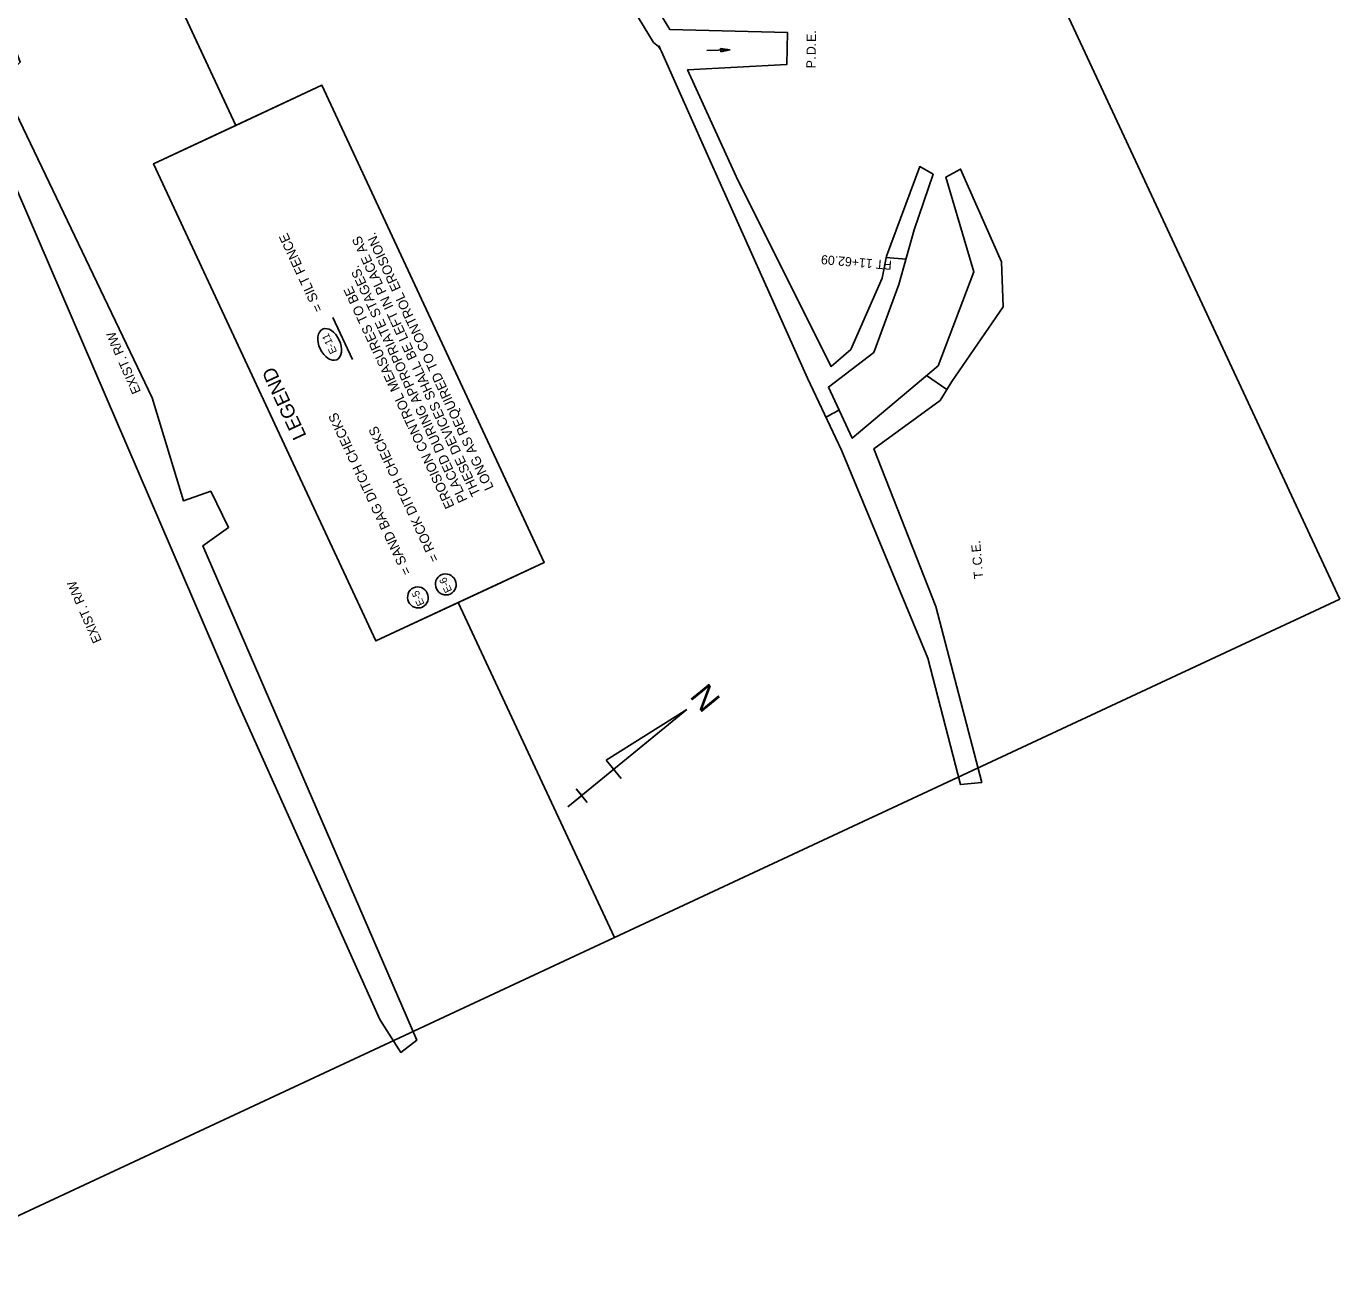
# Model space of a CAD drawing. Extents: x 964229 to 965790, y 1899262 to 1901428.
# Drawn here: x 964934 to 965790, y 1899262 to 1900076 of the extents above; entities that cross this region are included whole.
import ezdxf

# ---------------------------------------------------------------- set-up
doc = ezdxf.new("R2010")
doc.units = 0
for name, color, linetype in [('1', 7, 'Continuous'), ('43', 7, 'Continuous'), ('63', 7, 'Continuous'), ('Level 1', 7, 'Continuous'), ('Level 44', 7, 'Continuous'), ('NO PLOT', 7, 'Continuous'), ('R_Draft', 7, 'Continuous'), ('R_Horz Alg', 7, 'Continuous'), ('R_Horz Alg Annot', 7, 'Continuous')]:
    doc.layers.add(name, color=color, linetype=linetype)

msp = doc.modelspace()

# ---------------------------------------------------------------- linework, layer by layer
at = {"layer": '1'}
for p, q in [((965070.98, 1900011.03), (964950.03, 1900270.4)), ((965126.95, 1900037.14), (965017.24, 1899985.98)), ((965162.05, 1899675.42), (965017.24, 1899985.98)), ((965241.02, 1899712.24), (965162.05, 1899675.42)), ((965317.44, 1899482.49), (965215.79, 1899700.48))]:
    msp.add_line(p, q, dxfattribs=at)
msp.add_lwpolyline([(965241.02, 1899712.24), (965271.77, 1899726.58), (965126.95, 1900037.14)], dxfattribs=at)
at = {"layer": '43'}
for p, q in [((965386.67, 1900058.98), (965386.6, 1900061.13)), ((965386.6, 1900061.13), (965392.71, 1900060.24)), ((965392.71, 1900060.24), (965386.67, 1900058.98))]:
    msp.add_line(p, q, dxfattribs=at)
msp.add_lwpolyline([(965377.53, 1900059.77), (965392.71, 1900060.24)], dxfattribs=at)
at = {"layer": '63'}
for p, q in [((965287.19, 1899567.51), (965364.58, 1899630.84)), ((965364.58, 1899630.84), (965305.05, 1899582.13)), ((965364.58, 1899630.84), (965312.08, 1899597.82)), ((965312.08, 1899597.82), (965321.82, 1899585.92)), ((965287.19, 1899567.51), (965305.05, 1899582.13)), ((965296.12, 1899574.82), (965292.46, 1899579.28)), ((965292.46, 1899579.28), (965299.77, 1899570.35)), ((965287.19, 1899567.51), (965296.12, 1899574.82))]:
    msp.add_line(p, q, dxfattribs=at)
at = {"layer": 'Level 1'}
for centre, major_axis, ratio in [((965132.03, 1899868.45), (-4.63, 9.93), 0.622952), ((965207.6, 1899712.22), (2.91, -6.24), 0.97521), ((965189.47, 1899703.76), (2.91, -6.24), 0.97521)]:
    msp.add_ellipse(centre, major_axis=major_axis, ratio=ratio, dxfattribs=at)
at = {"layer": 'Level 44'}
msp.add_lwpolyline([(965146.86, 1899858.74), (965134.12, 1899886.04)], dxfattribs=at)
at = {"layer": 'NO PLOT'}
for points in [[(965789.77, 1899702.74), (965115.54, 1901148.63), (964643.21, 1900928.38), (964770.42, 1900655.58), (964831.6, 1900684.11), (965011.21, 1900298.93), (964950.03, 1900270.4), (965070.98, 1900011.03), (965126.95, 1900037.14), (965271.77, 1899726.58), (965215.79, 1899700.48), (965317.44, 1899482.49)], [(965789.77, 1899702.74), (965115.54, 1901148.63), (964643.21, 1900928.38), (964770.42, 1900655.58), (964831.6, 1900684.11), (965011.21, 1900298.93), (964950.03, 1900270.4), (965070.98, 1900011.03), (965126.95, 1900037.14), (965271.77, 1899726.58), (965215.79, 1899700.48), (965317.44, 1899482.49)], [(965789.77, 1899702.74), (965115.54, 1901148.63), (964643.21, 1900928.38), (964770.42, 1900655.58), (964831.6, 1900684.11), (965011.21, 1900298.93), (964950.03, 1900270.4), (965070.98, 1900011.03), (965126.95, 1900037.14), (965271.77, 1899726.58), (965215.79, 1899700.48), (965317.44, 1899482.49)], [(964845.11, 1899262.24), (964344.7, 1900335.36), (964389.48, 1900356.24), (964306.73, 1900533.69), (964319.96, 1900539.86), (964228.89, 1900735.17), (964643.21, 1900928.38), (964770.42, 1900655.58), (964700.63, 1900623.04), (964880.25, 1900237.86), (964950.03, 1900270.4), (965070.98, 1900011.03), (965017.24, 1899985.98), (965162.05, 1899675.42), (965215.79, 1899700.48), (965317.44, 1899482.49)], [(964845.11, 1899262.24), (964344.7, 1900335.36), (964389.48, 1900356.24), (964306.73, 1900533.69), (964319.96, 1900539.86), (964228.89, 1900735.17), (964643.21, 1900928.38), (964770.42, 1900655.58), (964700.63, 1900623.04), (964880.25, 1900237.86), (964950.03, 1900270.4), (965070.98, 1900011.03), (965017.24, 1899985.98), (965162.05, 1899675.42), (965215.79, 1899700.48), (965317.44, 1899482.49)], [(964845.11, 1899262.24), (964344.7, 1900335.36), (964389.48, 1900356.24), (964306.73, 1900533.69), (964319.96, 1900539.86), (964228.89, 1900735.17), (964643.21, 1900928.38), (964770.42, 1900655.58), (964700.63, 1900623.04), (964880.25, 1900237.86), (964950.03, 1900270.4), (965070.98, 1900011.03), (965017.24, 1899985.98), (965162.05, 1899675.42), (965215.79, 1899700.48), (965317.44, 1899482.49)], [(965347.31, 1900060.65), (965346.28, 1900062.47), (965346.24, 1900062.45), (965347.28, 1900060.63)]]:
    msp.add_lwpolyline(points, close=True, dxfattribs=at)
for points in [[(964743.2, 1900380.79), (964921.35, 1899985.44), (965071.82, 1899636.13), (965164.72, 1899429.12), (965178.4, 1899407.57), (965188.68, 1899415.47), (965049.43, 1899737.41), (965066.12, 1899749.34), (965054.6, 1899772.93), (965036.81, 1899766.7), (965016.41, 1899833.74), (964918.01, 1900039.22), (964930.54, 1900052.3), (964920.78, 1900078.79), (964905.36, 1900075.22), (964854.38, 1900212.3)], [(965291.71, 1900149.32), (965342.96, 1900065.1), (965346.17, 1900062.34), (965346.6, 1900062.65), (965346.62, 1900062.57), (965347.35, 1900060.46), (965347.33, 1900060.4), (965347.59, 1900060.06), (965348.08, 1900059.15), (965377.94, 1899992.37), (965443.26, 1899846.6), (965465.34, 1899799.73), (965521.63, 1899664.21), (965542.72, 1899581.94), (965556.69, 1899583.34), (965526.85, 1899697.97), (965486.39, 1899800.6), (965529.54, 1899831.99), (965537.16, 1899844.35), (965570.5, 1899893), (965569.59, 1899922.15), (965542.83, 1899982.57), (965533.26, 1899977.4), (965551.42, 1899915.79), (965528.16, 1899854.59), (965472.29, 1899807.41), (965456.78, 1899840.67), (965486.4, 1899863.29), (965502.76, 1899907.54), (965512.6, 1899943.12), (965525.02, 1899979.2), (965516.3, 1899984.29), (965494.55, 1899925.9), (965491.73, 1899911.55), (965471.45, 1899865.12), (965458.58, 1899854.19), (965398.05, 1899974.93), (965395.62, 1899980.14), (965365.04, 1900047.23), (965429.7, 1900050.61), (965430.14, 1900071.59), (965353.48, 1900073.53), (965312.89, 1900140.18)]]:
    msp.add_lwpolyline(points, dxfattribs=at)
at = {"layer": 'R_Horz Alg'}
msp.add_arc((965399.28, 1899932.96), 125, 296.5924, 301.02, dxfattribs=at)
at = {"layer": 'R_Horz Alg Annot'}
for points in [[(965507.32, 1899924.01), (965494.25, 1899925.09)], [(965520.7, 1899848.28), (965533.91, 1899839.07)]]:
    msp.add_lwpolyline(points, dxfattribs=at)

# ---------------------------------------------------------------- texts
at = {"layer": '63'}
msp.add_text('N', height=15.38, rotation=309.29267, dxfattribs=at).set_placement((965365.97, 1899639.26))
at = {"layer": 'Level 1'}
for s, height, p in [('= SILT FENCE', 6.25, (965127.79, 1899891.22)), ('THESE DEVICES SHALL BE LEFT IN PLACE AS ', 6.25, (965230.46, 1899771.28)), ('LONG AS REQUIRED TO CONTROL EROSION.', 6.25, (965238.99, 1899775.26)), ('PLACED DURING APPROPRIATE STAGES. ', 6.25, (965221.93, 1899767.3)), ('EROSION CONTROL MEASURES TO BE', 6.25, (965213.4, 1899763.33)), ('E-11 ', 4.876, (965136.91, 1899863.67)), ('= SAND BAG DITCH CHECKS', 6.25, (965185.32, 1899720.06)), ('= ROCK DITCH CHECKS', 6.25, (965203.44, 1899728.52)), ('E-6 ', 4.876, (965211.82, 1899708.2)), ('E-5 ', 4.876, (965193.87, 1899699.59))]:
    msp.add_text(s, height=height, rotation=115.00001, dxfattribs=at).set_placement(p)
at = {"layer": 'Level 44'}
msp.add_text('LEGEND', height=9.143, rotation=115.00001, dxfattribs=at).set_placement((965117.06, 1899809.06))
at = {"layer": 'R_Draft'}
for s, rotation, p in [('E', 89.12954, (965448.65, 1900065.34)), ('.', 89.12954, (965448.74, 1900070.73)), ('D', 89.12954, (965448.52, 1900056.75)), ('.', 89.12954, (965448.61, 1900062.41)), ('P', 89.12954, (965448.39, 1900048.15)), ('.', 89.12954, (965448.48, 1900053.82)), ('EXIST. R/W', 113.66592, (965009.21, 1899837.83)), ('E', 94.92297, (965556.22, 1899733.42)), ('.', 94.92297, (965555.76, 1899738.79)), ('C', 94.92297, (965556.96, 1899724.86)), ('.', 94.92297, (965556.48, 1899730.5)), ('T', 94.92297, (965557.72, 1899716.1)), ('.', 94.92297, (965557.21, 1899721.94)), ('EXIST. R/W', 113.66592, (964983.66, 1899675.65))]:
    msp.add_text(s, height=6, rotation=rotation, dxfattribs=at).set_placement(p)
at = {"layer": 'R_Horz Alg Annot'}
msp.add_text('PT 11+62.09', height=6, rotation=175.26469, dxfattribs=at).set_placement((965498.29, 1899922.93))

doc.saveas('drawing.dxf')
